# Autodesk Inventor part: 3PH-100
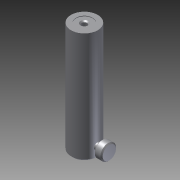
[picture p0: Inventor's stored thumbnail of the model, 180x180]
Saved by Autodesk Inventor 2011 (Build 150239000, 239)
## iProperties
Created: 2011-07
Part Number: 3PH-100
Document SubType Name: Modeling
Designer: vadybininkas6
Density: 1 g/cm^3
Author: vadybininkas6
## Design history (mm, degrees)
feature "Base1"
body "Solid1"
